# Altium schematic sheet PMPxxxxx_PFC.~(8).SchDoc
size 431 x 279 mm; Date: Not shown in title block; ApprovedBy: Not shown in title block; CheckedBy: Not shown in title block; Author: Not shown in title block; CompanyName: Not shown in title block; Engineer: Not shown in title block; Organization: Not shown in title block; Address1: Not shown in title block; Address2: Not shown in title block; Address3: Not shown in title block; Address4: Not shown in title block; DocumentNumber: 1; Revision: Use project parameter SCH_Rev; SheetNumber: 1; SheetTotal: 3; PageSetup: Record=PageOptions¦CenterHorizontal=True¦CenterVertical=True¦PrintScale=1.00¦XCorrection=1.00¦YCorrection=1.00¦PrintKind=0¦BorderSize=5000000¦LeftOffset=0¦BottomOffset=0¦Orientation=2¦PaperLength=1000¦PaperWidth=1000¦Scale=100¦PaperSource=15¦PrintQuality=600¦MediaType=1¦DitherType=10¦PaperKind=Letter¦PrintScaleMode=1
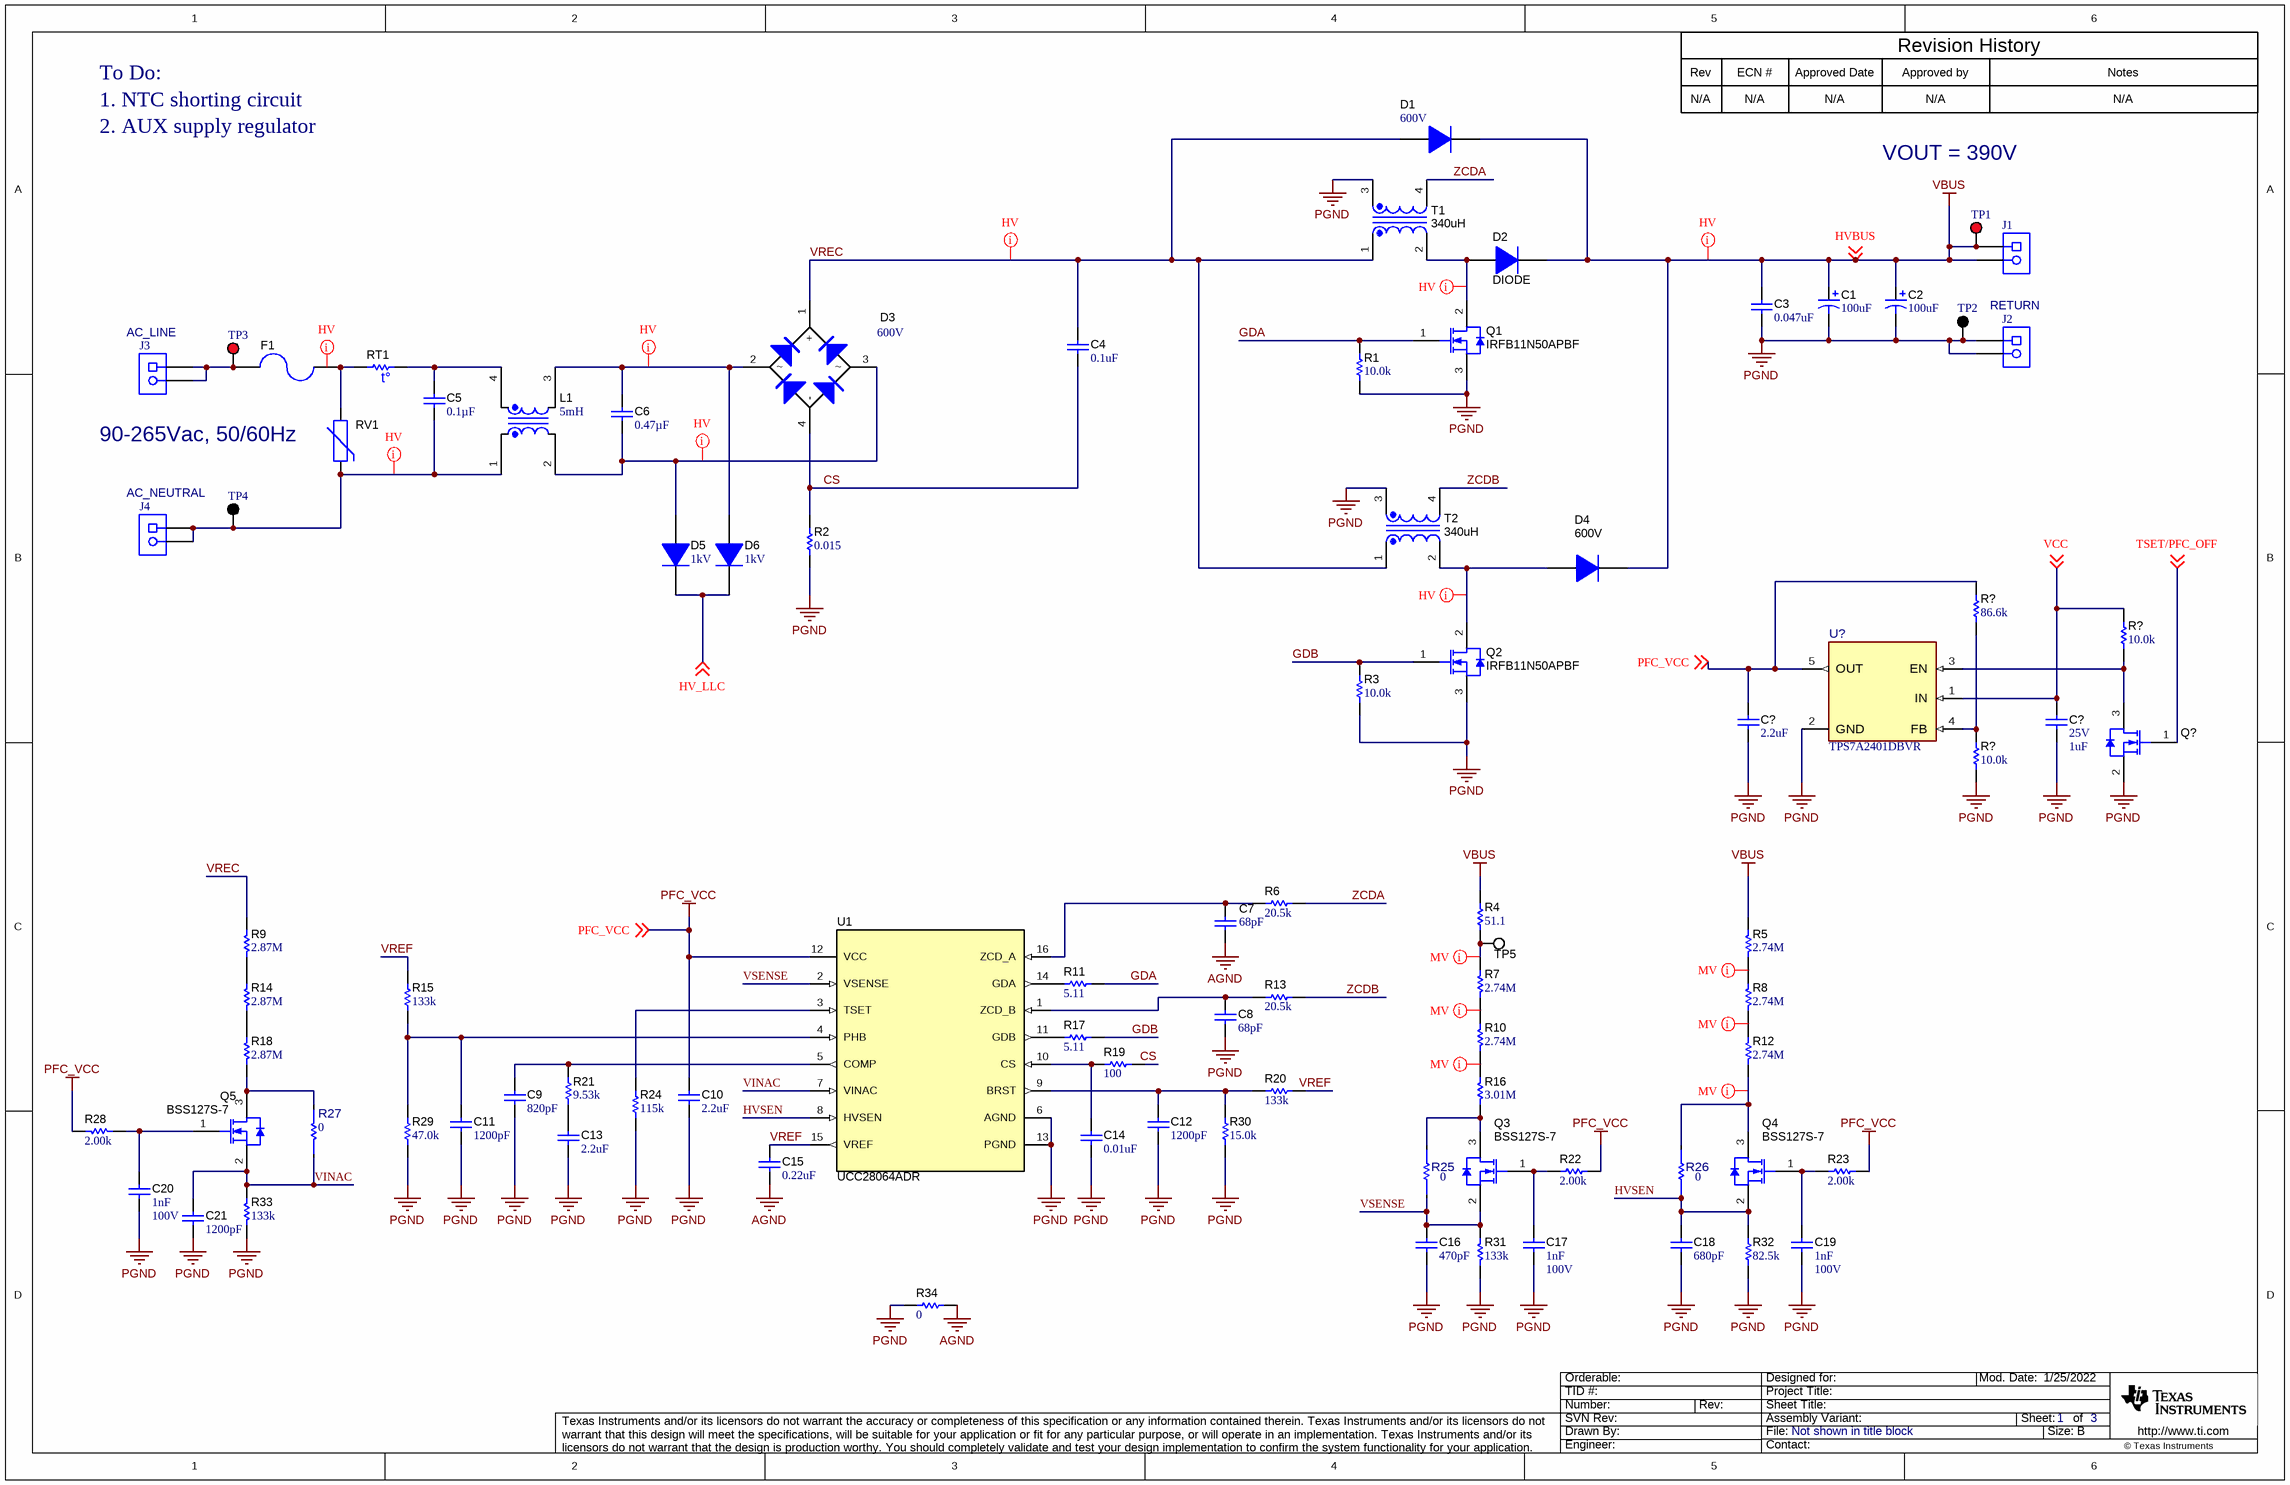
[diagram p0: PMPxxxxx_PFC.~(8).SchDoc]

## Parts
(Parts that share a designator on the sheet are numbered #1, #2 ... from top to bottom, then left to right.)
C1  ValueDisplayed: 100uF  [KXG_1800x4000_horizontalUp]  (hidden comment: Cap_Polarized)
C2  ValueDisplayed: 100uF  [KXG_1800x4000_horizontalDown]  (hidden comment: Cap_Polarized)
C3  ValueDisplayed: 0.047uF  [ECQE_1200x1450x650]  (hidden comment: Capacitor)
C4  ValueDisplayed: 0.1uF  [CAPRR1500W60L1750T550H1250]  (hidden comment: Capacitor)
C5  ValueDisplayed: 0.1µF  [Kemet_1800x500x1100]  (hidden comment: F863BC104K310Z)
C6  ValueDisplayed: 0.47µF  [PHE840M_2600x800x1600]  (hidden comment: PHE840MY6470MD14R06L2)
C7  ValueDisplayed: 68pF  [0805_HV]  (hidden comment: Capacitor)
C8  ValueDisplayed: 68pF  [0805_HV]  (hidden comment: Capacitor)
C9  ValueDisplayed: 820pF  [0805_HV]  (hidden comment: Capacitor)
C10  ValueDisplayed: 2.2uF  [0805_HV]  (hidden comment: Capacitor)
C11  ValueDisplayed: 1200pF  [0805_HV]  (hidden comment: Capacitor)
C12  ValueDisplayed: 1200pF  [0805_HV]  (hidden comment: Capacitor)
C13  ValueDisplayed: 2.2uF  [0805_HV]  (hidden comment: Capacitor)
C14  ValueDisplayed: 0.01uF  [0805_HV]  (hidden comment: Capacitor)
C15  ValueDisplayed: 0.22uF  [1206]  (hidden comment: Capacitor)
C16  ValueDisplayed: 470pF  [0805_HV]  (hidden comment: Capacitor)
C17  Cap_F: 1nF  VDC_V: 100V  [0603]  (hidden comment: C1608X7R2A102K080AA)
C18  ValueDisplayed: 680pF  [0805_HV]  (hidden comment: Capacitor)
C19  Cap_F: 1nF  VDC_V: 100V  [0603]  (hidden comment: C1608X7R2A102K080AA)
C20  Cap_F: 1nF  VDC_V: 100V  [0603]  (hidden comment: C1608X7R2A102K080AA)
C21  ValueDisplayed: 1200pF  [0805_HV]  (hidden comment: Capacitor)
C?#1  ValueDisplayed: 2.2uF  [0805_HV]  (hidden comment: Capacitor)
C?#2  VDC_V: 25V  ValueDisplayed: 1uF  [0603]  (hidden comment: C1608X5R1E105K080AC)
D1  Vr_V: 600V  [SMC]  (hidden comment: DIODE)
D2  DIODE  [SMC]
D3  Vr_V: 600V  [GBU_Horizontal_Down_Standoff2300]  (hidden comment: GBU6J)
D4  600V  [SMC]
D5  Vr_V: 1kV  [DO-41]  (hidden comment: 1N4007-E3/73)
D6  Vr_V: 1kV  [DO-41]  (hidden comment: 1N4007-E3/73)
F1  0216008.MXEP  [FUSE_0216]  (value not drawn)
J1  Receptacle_2x1  [On-Shore_ED120_2DS]  (value not drawn)
J2  Receptacle_2x1  [On-Shore_ED120_2DS]  (value not drawn)
J3  Receptacle_2x1  [On-Shore_ED120_2DS]  (value not drawn)
J4  Receptacle_2x1  [On-Shore_ED120_2DS]  (value not drawn)
L1  ValueDisplayed: 5mH  [8100_8109-8114]  (hidden comment: INDUCTOR_COUPLED_12_43)
Q1  IRFB11N50APBF  [TO-220AB_Horizontal_100mil_Standoff2300]
Q2  IRFB11N50APBF  [TO-220AB_Horizontal_100mil_Standoff2300]
Q3  BSS127S-7  [SOT-23]
Q4  BSS127S-7  [SOT-23]
Q5  BSS127S-7  [SOT-23]
Q?  2N7002-7-F  [SOT-23]  (value not drawn)
R1  ValueDisplayed: 10.0k  [0805_HV]  (hidden comment: Resistor)
R2  ValueDisplayed: 0.015  [2010]  (hidden comment: Resistor)
R3  ValueDisplayed: 10.0k  [0805_HV]  (hidden comment: Resistor)
R4  ValueDisplayed: 51.1  [0805_HV]  (hidden comment: Resistor)
R5  ValueDisplayed: 2.74M  [0805_HV]  (hidden comment: Resistor)
R6  ValueDisplayed: 20.5k  [0805_HV]  (hidden comment: Resistor)
R7  ValueDisplayed: 2.74M  [0805_HV]  (hidden comment: Resistor)
R8  ValueDisplayed: 2.74M  [0805_HV]  (hidden comment: Resistor)
R9  ValueDisplayed: 2.87M  [0805_HV]  (hidden comment: Resistor)
R10  ValueDisplayed: 2.74M  [0805_HV]  (hidden comment: Resistor)
R11  ValueDisplayed: 5.11  [0805_HV]  (hidden comment: Resistor)
R12  ValueDisplayed: 2.74M  [0805_HV]  (hidden comment: Resistor)
R13  ValueDisplayed: 20.5k  [0805_HV]  (hidden comment: Resistor)
R14  ValueDisplayed: 2.87M  [0805_HV]  (hidden comment: Resistor)
R15  ValueDisplayed: 133k  [0805_HV]  (hidden comment: CRCW0805133KFKEA)
R16  ValueDisplayed: 3.01M  [0805_HV]  (hidden comment: Resistor)
R17  ValueDisplayed: 5.11  [0805_HV]  (hidden comment: Resistor)
R18  ValueDisplayed: 2.87M  [0805_HV]  (hidden comment: Resistor)
R19  ValueDisplayed: 100  [0805_HV]  (hidden comment: Resistor)
R20  ValueDisplayed: 133k  [0805_HV]  (hidden comment: CRCW0805133KFKEA)
R21  ValueDisplayed: 9.53k  [0805_HV]  (hidden comment: Resistor)
R22  ValueDisplayed: 2.00k  [0603]  (hidden comment: RC0603FR-072KL)
R23  ValueDisplayed: 2.00k  [0603]  (hidden comment: RC0603FR-072KL)
R24  ValueDisplayed: 115k  [0805_HV]  (hidden comment: CRCW0805115KFKEA)
R25  value 0  [FP-RMCF1206ZT0R00_1206-MFG]  (hidden comment: RMCF1206ZT0R00)
R26  value 0  [FP-RMCF1206ZT0R00_1206-MFG]  (hidden comment: RMCF1206ZT0R00)
R27  value 0  [FP-RMCF1206ZT0R00_1206-MFG]  (hidden comment: RMCF1206ZT0R00)
R28  ValueDisplayed: 2.00k  [0603]  (hidden comment: RC0603FR-072KL)
R29  ValueDisplayed: 47.0k  [0805_HV]  (hidden comment: Resistor)
R30  ValueDisplayed: 15.0k  [0805_HV]  (hidden comment: CRCW080515K0FKEA)
R31  ValueDisplayed: 133k  [0805_HV]  (hidden comment: Resistor)
R32  ValueDisplayed: 82.5k  [0805_HV]  (hidden comment: Resistor)
R33  ValueDisplayed: 133k  [0805_HV]  (hidden comment: CRCW0805133KFKEA)
R34  ValueDisplayed: 0  [2512]  (hidden comment: Resistor)
R?#1  ValueDisplayed: 86.6k  [0603]  (hidden comment: RC0603FR-0786K6L)
R?#2  ValueDisplayed: 10.0k  [0603]  (hidden comment: M55342K12B10E0T)
R?#3  ValueDisplayed: 10.0k  [0603]  (hidden comment: M55342K12B10E0T)
RT1  CL-40  [Thermistor_CL-40]  (value not drawn)
RV1  Varistor_MetalOxide  [VAR_S10K275E2]  (value not drawn)
T1  340uH  [EATON_CTX16-17769-R]
T2  340uH  [EATON_CTX16-17769-R]
TP1  5010  [Keystone5010]  (value not drawn)
TP2  5011  [Keystone5011]  (value not drawn)
TP3  5010  [Keystone5010]  (value not drawn)
TP4  5011  [Keystone5011]  (value not drawn)
TP5  5002  [Keystone5002]  (value not drawn)
U1  UCC28064ADR  [D0016A_N]
U?  TPS7A2401DBVR  [DBV0005A-MFG]

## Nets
AGND: C7.2 C15.2 R34.1
PFC_VCC: C10.2 C?#1.2 R22.2 R23.2 R28.2 R?#1.1 U1.12(VCC) U?.5(OUT) ; off-sheet PFC_VCC
PGND: C1.2(-) C2.2(-) C3.2 C8.1 C9.1 C10.1 C11.2 C12.2 C13.2 C14.2 C16.2 C17.2 C18.2 C19.2 C20.2 C21.1 C?#1.1 C?#2.2 J2.1 J2.2 Q1.3(S) Q2.3(S) Q?.2(S) R1.1 R2.1 R3.1 R24.1 R29.1 R30.1 R31.1 R32.1 R33.1 R34.2 R?#3.1 T1.3 T2.3 TP2.1 U1.6(AGND) U1.13(PGND) U?.2(GND)
VBUS: C1.1(+) C2.1(+) C3.1 D1.1(K) D2.1(K) D4.1(K) J1.1 J1.2 R4.2 R5.2 TP1.1 ; off-sheet HVBUS  [also labelled HVBUS]
CS: C4.2 D3.4(-) R2.2 R19.2
GDA: Q1.1(G) R1.2 R11.2
GDB: Q2.1(G) R3.2 R17.2
HV_LLC: D5.1(K) D6.1(K) ; off-sheet HV_LLC
HVSEN: C18.1 Q4.2(S) R26.1 R32.2 U1.8(HVSEN)
TSET/PFC_OFF: Q?.1(G) ; off-sheet TSET/PFC_OFF
VCC: C?#2.1 R?#2.2 U?.1(IN) ; off-sheet VCC
VINAC: C21.2 Q5.2(S) R27.1 R33.2 U1.7(VINAC)
VREC: C4.1 D1.2(A) D3.1(+) R9.1 T1.1 T2.1
VREF: C15.1 R15.2 R20.2 U1.15(VREF)
VSENSE: C16.1 Q3.2(S) R25.1 R31.2 U1.2(VSENSE)
ZCDA: R6.1 T1.4
ZCDB: R13.2 T2.4
NetC5_1: C5.1 L1.4 RT1.2
NetC5_2: C5.2 J4.1 J4.2 L1.1 RV1.2 TP4.1
NetC6_1: C6.1 D3.2 D6.2(A) L1.3
NetC6_2: C6.2 D3.3 D5.2(A) L1.2
NetC7_1: C7.1 R6.2 U1.16(ZCD_A)
NetC8_2: C8.2 R13.1 U1.1(ZCD_B)
NetC9_2: C9.2 R21.2 U1.5(COMP)
NetC11_1: C11.1 R15.1 R29.2 U1.4(PHB)
NetC12_1: C12.1 R20.1 R30.2 U1.9(BRST)
NetC13_1: C13.1 R21.1
NetC14_1: C14.1 R19.1 U1.10(CS)
NetC17_1: C17.1 Q3.1(G) R22.1
NetC19_1: C19.1 Q4.1(G) R23.1
NetC20_1: C20.1 Q5.1(G) R28.1
NetD2_2: D2.2(A) Q1.2(D) T1.2
NetD4_2: D4.2(A) Q2.2(D) T2.2
NetF1_1: F1.1 RT1.1 RV1.1
NetF1_2: F1.2 J3.1 J3.2 TP3.1
NetQ3_3: Q3.3(D) R16.2 R25.2
NetQ4_3: Q4.3(D) R12.1 R26.2
NetQ5_3: Q5.3(D) R18.1 R27.2
NetQ?_3: Q?.3(D) R?#2.1 U?.3(EN)
NetR4_1: R4.1 R7.1 TP5.1
NetR5_1: R5.1 R8.2
NetR7_2: R7.2 R10.1
NetR8_1: R8.1 R12.2
NetR9_2: R9.2 R14.1
NetR10_2: R10.2 R16.1
NetR11_1: R11.1 U1.14(GDA)
NetR14_2: R14.2 R18.2
NetR17_1: R17.1 U1.11(GDB)
NetR24_2: R24.2 U1.3(TSET)
NetR?#1_2: R?#1.2 R?#3.2 U?.4(FB)

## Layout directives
net class HV: (no net found under the mark), NetC5_2, NetC6_1, NetC6_2, NetD2_2, NetD4_2, VBUS, VREC
net class MV: NetQ4_3, NetR4_1, NetR5_1, NetR7_2, NetR8_1, NetR10_2

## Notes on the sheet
- To Do:
- Rev
- N/A
- ECN #
- Approved Date
- Approved by
- Revision History
- Notes
- 1. NTC shorting circuit
- 2. AUX supply regulator
- VOUT = 390V
- (near J3) AC_LINE
- RETURN
- 90-265Vac, 50/60Hz
- (near J4) AC_NEUTRAL

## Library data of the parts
C1 C2 = CMP-0010042-2: CAP, AL, 100 uF, 450 V, +/- 20%, TH; PartNumber: EKXG451ELL101MM40S; Manufacturer: Chemi-Con; Polarized: Y; CompType: Capacitor; Value: 100uF; U/M: EA; Cap_F: 100µF; Value1: Unknown; VDC_V: 450V; IRMS_A: 8dA; TaMin_C: -25°C; TaMax_C: 105°C; Cap_Case: 18x40mm; SizeAreaWB_mm2: 400; SizeArea_mm2: 324; SizeX_mm: 18; SizeZ_mm: 41.5; AEC Category: Q200; AEC Qualified: N
C3 = CMP-0012494-3: CAP, Film, 0.047 uF, 630 V, +/- 10%, TH; PartNumber: ECQ-E6473KF; Manufacturer: Panasonic; Polarized: N; Cap_F: 47nF; Value1: Unknown; VDC_V: 630V; TaMin_C: -40°C; TaMax_C: 105°C; Cap_Case: 12x14.5x6.5mm; SizeAreaWB_mm2: 119; SizeArea_mm2: 78; SizeX_mm: 12; SizeY_mm: 6.5; SizeZ_mm: 14.5; AEC Category: Q200
C4 = CMP-0012496-3: CAP, Film, 0.1 uF, 275 V, +/- 20%, TH; PartNumber: ECQ-U2A104ML; Manufacturer: Panasonic; Polarized: N; Value: 0.1uF; Cap_F: 100nF; Value1: Unknown; VDC_V: 275V; TaMin_C: -40°C; TaMax_C: 100°C; Cap_Case: Radial 17.5x5.5x12.5; AEC Category: Q200
C5 = CMP-0079307-2: CAP, Film, 0.1 µF, X2 310 VAC, +/- 10%, AEC-Q200 Grade 1, TH; Manufacturer: Kemet; Cap_F: 100nF; SizeAreaWB_mm2: 140; SizeArea_mm2: 90; AEC Qualified: Y; AEC Category: Q200; Value: 0.1uF; TaMax_C: 110°C; SizeZ_mm: 11.1; AEC Grade: 1; Polarized: N; TaMin_C: -40°C; SizeY_mm: 5; CompType: Capacitor; SizeX_mm: 18; Cap_Case: 18x5x11mm; VAC_X: 310
C6 = CMP-0079470-1: CAP, Film, 0.47 µF, 760 V,+/- 20%, TH; Manufacturer: Kemet; Cap_F: 470nF; SizeAreaWB_mm2: 280; SizeArea_mm2: 208; AEC Qualified: N; AEC Category: Q200; Value: 0.47uF; TaMax_C: 105°C; SizeZ_mm: 16; TaMin_C: -55°C; VDC_V: 760V; SizeY_mm: 8; CompType: Capacitor; SizeX_mm: 26; Cap_Case: 26x8x16mm
C7 C8 = CMP-0007622-2: CAP, CERM, 68 pF, 50 V, +/- 5%, C0G/NP0, 0805; PartNumber: 08055A680JAT2A; Manufacturer: AVX; Polarized: N; Value: 68pF; U/M: EA; ESR_ohm: 4.5d; Value1: 0.45 ohm; VDC_V: 50V; TaMin_C: -55°C; TaMax_C: 125°C; Cap_Case: 0805; SizeArea_mm2: 2.5; SizeAreaWB_mm2: 6.75; SizeX_mm: 2; SizeY_mm: 1.25; SizeZ_mm: 1.45; AEC Category: Q200
C9 = CMP-0008153-2: CAP, CERM, 820 pF, 25 V, +/- 10%, X7R, 0805; PartNumber: GRM216R71E821KA01D; Manufacturer: MuRata; Polarized: N; Value: 820pF; U/M: EA; Value1: Unknown; VDC_V: 25V; TaMin_C: -55°C; TaMax_C: 125°C; Cap_Case: 0805; SizeArea_mm2: 2.5; SizeAreaWB_mm2: 6.75; SizeX_mm: 2; SizeY_mm: 1.25; SizeZ_mm: 1.45; AEC Category: Q200
C10 C13 C?#1 = CMP-0007877-2: CAP, CERM, 2.2 uF, 50 V, +/- 10%, X7R, 0805; PartNumber: C2012X7R1H225K125AC; Manufacturer: TDK; Polarized: N; Value: 2.2uF; U/M: EA; Cap_F: 2.2µF; ESR_ohm: 3.66m; Value1: 0.00366 ohm; VDC_V: 50V; IRMS_A: 3.41207A; TaMin_C: -55°C; TaMax_C: 125°C; Cap_Case: 0805; SizeArea_mm2: 2.5; SizeAreaWB_mm2: 6.75; SizeX_mm: 2; SizeY_mm: 1.25; SizeZ_mm: 1.45; AEC Category: Q200
C11 C12 C21 = CMP-0008142-2: CAP, CERM, 1200 pF, 25 V, +/- 10%, X7R, 0805; PartNumber: GRM216R71E122KA01D; Manufacturer: MuRata; Polarized: N; Value: 1200pF; U/M: EA; Cap_F: 1.2nF; Value1: Unknown; VDC_V: 25V; TaMin_C: -55°C; TaMax_C: 125°C; Cap_Case: 0805; SizeArea_mm2: 2.5; SizeAreaWB_mm2: 6.75; SizeX_mm: 2; SizeY_mm: 1.25; SizeZ_mm: 1.45; AEC Category: Q200
C14 = CMP-0007629-2: CAP, CERM, 0.01 uF, 50 V, +/- 5%, X7R, 0805; PartNumber: 08055C103JAT2A; Manufacturer: AVX; Polarized: N; Value: 0.01uF; U/M: EA; Cap_F: 10nF; ESR_ohm: 0.078; Value1: 0.078 ohm; VDC_V: 50V; TaMin_C: -55°C; TaMax_C: 125°C; Cap_Case: 0805; SizeArea_mm2: 2.5; SizeAreaWB_mm2: 6.75; SizeX_mm: 2; SizeY_mm: 1.25; SizeZ_mm: 1.45; AEC Category: Q200
C15 = CMP-0008995-2: CAP, CERM, 0.22 uF, 50 V, +/- 10%, X7R, 1206; PartNumber: GRM31MR71H224KA01L; Manufacturer: MuRata; Polarized: N; Value: 0.22uF; U/M: EA; Cap_F: 220nF; Value1: Unknown; VDC_V: 50V; TaMin_C: -55°C; TaMax_C: 125°C; SizeArea_mm2: 5.12; SizeAreaWB_mm2: 10.92; SizeX_mm: 3.2; SizeY_mm: 1.6; SizeZ_mm: 1.35; AEC Category: Q200
C16 = CMP-0008150-2: CAP, CERM, 470 pF, 25 V, +/- 10%, X7R, 0805; PartNumber: GRM216R71E471KA01D; Manufacturer: MuRata; Polarized: N; Value: 470pF; U/M: EA; Value1: Unknown; VDC_V: 25V; TaMin_C: -55°C; TaMax_C: 125°C; Cap_Case: 0805; SizeArea_mm2: 2.5; SizeAreaWB_mm2: 6.75; SizeX_mm: 2; SizeY_mm: 1.25; SizeZ_mm: 1.45; AEC Category: Q200
C17 C19 C20 = CMP-0007053-4: CAP, CERM, 1000 pF, 100 V, +/- 10%, X7R, 0603; Manufacturer: TDK; TaMin_C: -55°C; Polarized: N; SizeAreaWB_mm2: 4.68; Value1: Unknown; U/M: EA; Value: 1000pF; TaMax_C: 125°C; SizeZ_mm: 1; SizeX_mm: 1.6; SizeY_mm: 0.8; SizeArea_mm2: 1.28; AEC Category: Q200
C18 = CMP-0007693-2: CAP, CERM, 680 pF, 25 V, +/- 10%, X7R, 0805; PartNumber: 885012207059; Manufacturer: Wurth Elektronik; Polarized: N; Value: 680pF; U/M: EA; Value1: Unknown; VDC_V: 25V; TaMin_C: -55°C; TaMax_C: 125°C; Cap_Case: 0805; SizeArea_mm2: 2.5; SizeAreaWB_mm2: 6.75; SizeX_mm: 2; SizeY_mm: 1.25; SizeZ_mm: 1.45; AEC Category: Q200
C?#2 = CMP-0007006-5: CAP, CERM, 1 uF, 25 V, +/- 10%, X5R, 0603; Manufacturer: TDK; TaMin_C: -55°C; Polarized: N; SizeAreaWB_mm2: 4.68; Value1: Unknown; U/M: EA; Value: 1uF; TaMax_C: 85°C; SizeZ_mm: 1; SizeX_mm: 1.6; SizeY_mm: 0.8; SizeArea_mm2: 1.28; Cap_F: 1µF; AEC Category: Q200
D1 D2 = CMP-0076905-1: Diode, Ultrafast, 600 V, 3 A, SMC; PartNumber: MURS360T3G; Manufacturer: ON Semiconductor; U/M: EA; Vf_V: 1.25V; Value: 600V; Value1: 3A; TJmax_C: 175°C; RJC_CperW: 11.0; SizeAreaWB_mm2: 83.2686; SizeArea_mm2: 50.5686; SizeX_mm: 8.13; SizeY_mm: 6.22; SizeZ_mm: 2.6; AEC Category: Q101; Green_Lifecycle: Active; Green_REACh: Passed
D3 = CMP-0029269-2: Diode, Switching-Bridge, 600 V, 6 A, TH; Manufacturer: Fairchild Semiconductor; U/M: EA; Vf_V: 1V; Value: 600V; Value1: 6A; TJmax_C: 150°C; RJC_CperW: 3.1; SizeAreaWB_mm2: 130.5915; SizeArea_mm2: 75.6315; SizeX_mm: 22.05; SizeY_mm: 3.43; SizeZ_mm: 21.55; AEC Category: Q101; AEC Qualified: N; Green_Lifecycle: Active; Green_REACh: Passed
D4 = CMP-0076905-1: Diode, Ultrafast, 600 V, 3 A, SMC; PartNumber: MURS360T3G; Manufacturer: ON Semiconductor; U/M: EA; Vf_V: 1.25V; Value1: 3A; TJmax_C: 175°C; RJC_CperW: 11.0; SizeAreaWB_mm2: 83.2686; SizeArea_mm2: 50.5686; SizeX_mm: 8.13; SizeY_mm: 6.22; SizeZ_mm: 2.6; AEC Category: Q101; Green_Lifecycle: Active; Green_REACh: Passed
D5 D6 = CMP-0029188-2: Diode, P-N, 1000 V, 1 A, TH; Manufacturer: Vishay-Semiconductor; Io_A: 1A; SizeAreaWB_mm2: 43.424; TJmax_C: 150°C; Value: 1000V; SizeZ_mm: 23.4; SizeX_mm: 7.2; SizeY_mm: 2.72; Vf_V: 1.1V; SizeArea_mm2: 19.584; AEC Qualified: N; AEC Category: Q101
F1 = CMP-0079917-1: Fuse, 8 A, 250 VAC, TH; Manufacturer: Littelfuse; VAC_V: 250V; Rtyp_Ohm: 0.0123; MeltingTyp: 64.315; Irating_A: 8A; Interrupt_AC: 1.5kA
J1-J4 = CMP-0074910-1: Terminal Block, 5.08 mm, 2x1, Brass, TH; PartNumber: ED120/2DS; Manufacturer: On-Shore Technology; Pitch_mm: 5.08; Gender: Female; Shrouded: N; Row_Count: 1; Current_A: 15A; Voltage_V: 300V; Cert_CULUS: Y; Green_Lifecycle: Not Set; Green_REACh: Incomplete; CNHeader: False; CT: True
L1 = CMP-0076835-1: Coupled inductor, 5 mH, 8.9 A, 0.022 ohm, TH; PartNumber: 8113-RC; Manufacturer: Bourns; Value: 5mH; DCR_ohm: 0.022; Green_Lifecycle: Not Set; Green_REACh: Incomplete; AEC Category: Q200
Q1 Q2 = CMP-0001125-3: MOSFET, N-CH, 500 V, 11 A, AEC-Q101, TO-220AB; Alternate Manufacturer: None; Manufacturer: Vishay-Siliconix; SizeZ_mm: 19.4; ChType: N; Value2: 52 nC; VdsMax_V: 500V; SizeX_mm: 10.2; SizeY_mm: 4.5; Vgs_V: 30V; AEC Qualified: Y; Value: 500V; SizeArea_mm2: 45.9; AEC Category: Q101; IdsMax_A: 11A; SizeAreaWB_mm2: 79.3; U/M: EA; QgTyp_nC: 52
Q3-Q5 = CMP-0001149-3: MOSFET, N-CH, 600 V, 0.05 A, SOT-23; Alternate Manufacturer: None; Manufacturer: Diodes Inc.; SizeZ_mm: 1.1; ChType: N; Value2: 1.08 nC; VdsMax_V: 600V; SizeX_mm: 2.5; SizeY_mm: 3; Vgs_V: 20V; QgTyp_nC: 1.08; Value: 600V; SizeArea_mm2: 7.5; AEC Category: Q101; IdsMax_A: 50mA; SizeAreaWB_mm2: 14; U/M: EA
Q? = CMP-0000769-1: MOSFET, N-CH, 60 V, 0.17 A, SOT-23; Alternate Manufacturer: None; Manufacturer: Diodes Inc.; SizeZ_mm: 1.1; ChType: N; Value2: 223 nC; Value1: 7; VdsMax_V: 60V; SizeX_mm: 2.5; SizeY_mm: 3; Vgs_V: 20V; Value: 60V; Rdson45_ohm: 7.5; AEC Category: Q101; IdsMax_A: 1.7dA; SizeAreaWB_mm2: 14; U/M: EA; QgTyp_nC: 223
R1 R3 = CMP-0020842-3: RES, 10.0 k, 1%, 0.125 W, AEC-Q200 Grade 0, 0805; PartNumber: CRCW080510K0FKEA; Manufacturer: Vishay-Dale; Value: 10.0k; Res_ohm: 10k; Value_Code: 10k0; Power_W: 125mW; Value2: 0.125W; VDC_V: 150V; TempCo: 100 ppm/C; SizeArea_mm2: 2.5; SizeX_mm: 2; SizeY_mm: 1.25; SizeZ_mm: 1.45; EIA_Code: E96; AEC Category: Q200; AEC Qualified: Y; AEC Grade: 0
R2 = CMP-0016558-2: RES, 0.015, 1%, 0.5 W, 2010; PartNumber: WSL2010R0150FEA; Manufacturer: Vishay-Dale; Value: 0.015; Value_Code: R015; Power_W: 500mW; Value2: 0.5W; TempCo: 75 ppm/C; SizeArea_mm2: 12.5; SizeX_mm: 5; SizeY_mm: 2.5; SizeZ_mm: 1.66; EIA_Code: E96; U/M: EA; AEC Category: Q200
R4 = CMP-0020156-2: RES, 51.1, 0.1%, 0.125 W, 0805; PartNumber: RT0805BRD0751R1L; Manufacturer: Yageo America; Value: 51.1; Value_Code: 51R1; Power_W: 125mW; Value2: 0.125W; VDC_V: 150V; TempCo: 25 ppm/C; SizeArea_mm2: 2.5; SizeX_mm: 2; SizeY_mm: 1.25; SizeZ_mm: 1.45; EIA_Code: E192; U/M: EA; AEC Category: Q200
R5 R7 R8 R10 R12 = CMP-0021137-3: RES, 2.74 M, 1%, 0.125 W, AEC-Q200 Grade 0, 0805; PartNumber: CRCW08052M74FKEA; Manufacturer: Vishay-Dale; Value: 2.74Meg; Value_Code: 2M74; Power_W: 125mW; Value2: 0.125W; VDC_V: 150V; TempCo: 100 ppm/C; SizeArea_mm2: 2.5; SizeX_mm: 2; SizeY_mm: 1.25; SizeZ_mm: 1.45; EIA_Code: E96; AEC Category: Q200; AEC Qualified: Y; AEC Grade: 0
R6 R13 = CMP-0021043-3: RES, 20.5 k, 1%, 0.125 W, AEC-Q200 Grade 0, 0805; PartNumber: CRCW080520K5FKEA; Manufacturer: Vishay-Dale; Value: 20.5k; Value_Code: 20k5; Power_W: 125mW; Value2: 0.125W; VDC_V: 150V; TempCo: 100 ppm/C; SizeArea_mm2: 2.5; SizeX_mm: 2; SizeY_mm: 1.25; SizeZ_mm: 1.45; EIA_Code: E96; AEC Category: Q200; AEC Qualified: Y; AEC Grade: 0
R9 R14 R18 = CMP-0021139-3: RES, 2.87 M, 1%, 0.125 W, AEC-Q200 Grade 0, 0805; PartNumber: CRCW08052M87FKEA; Manufacturer: Vishay-Dale; Value: 2.87Meg; Value_Code: 2M87; Power_W: 125mW; Value2: 0.125W; VDC_V: 150V; TempCo: 100 ppm/C; SizeArea_mm2: 2.5; SizeX_mm: 2; SizeY_mm: 1.25; SizeZ_mm: 1.45; EIA_Code: E96; AEC Category: Q200; AEC Qualified: Y; AEC Grade: 0
R11 R17 = CMP-0021358-3: RES, 5.11, 1%, 0.125 W, AEC-Q200 Grade 0, 0805; PartNumber: CRCW08055R11FKEA; Manufacturer: Vishay-Dale; Value: 5.11; Value_Code: 5R11; Power_W: 125mW; Value2: 0.125W; VDC_V: 150V; TempCo: 100 ppm/C; SizeArea_mm2: 2.5; SizeX_mm: 2; SizeY_mm: 1.25; SizeZ_mm: 1.45; EIA_Code: E96; AEC Category: Q200; AEC Qualified: Y; AEC Grade: 0
R15 R20 R33 = CMP-0020881-3: RES, 133 k, 1%, 0.125 W, AEC-Q200 Grade 0, 0805; Manufacturer: Vishay-Dale; Power_W: 125mW; TempCo: 100 ppm/C; Value: 133k; EIA_Code: E96; SizeX_mm: 2; SizeY_mm: 1.25; SizeZ_mm: 1.45; Value2: 0.125W; SizeArea_mm2: 2.5; AEC Qualified: Y; VDC_V: 150V; AEC Category: Q200; AEC Grade: 0
R16 = CMP-0021219-4: RES, 3.01 M, 1%, 0.125 W, AEC-Q200 Grade 0, 0805; PartNumber: CRCW08053M01FKEA; Manufacturer: Vishay-Dale; Value: 3.01Meg; Value_Code: 3M01; Power_W: 125mW; Value2: 0.125W; VDC_V: 150V; TempCo: 100 ppm/C; SizeArea_mm2: 2.5; SizeX_mm: 2; SizeY_mm: 1.25; SizeZ_mm: 1.45; EIA_Code: E96; AEC Category: Q200; AEC Qualified: Y; AEC Grade: 0
R19 = CMP-0020835-3: RES, 100, 1%, 0.125 W, AEC-Q200 Grade 0, 0805; PartNumber: CRCW0805100RFKEA; Manufacturer: Vishay-Dale; Value: 100; Value_Code: 100R; Power_W: 125mW; Value2: 0.125W; VDC_V: 150V; TempCo: 100 ppm/C; SizeArea_mm2: 2.5; SizeX_mm: 2; SizeY_mm: 1.25; SizeZ_mm: 1.45; EIA_Code: E96; AEC Category: Q200; AEC Qualified: Y; AEC Grade: 0
R21 = CMP-0021817-2: RES, 9.53 k, 1%, 0.125 W, 0805; PartNumber: ERJ-6ENF9531V; Manufacturer: Panasonic; Value: 9.53k; Value_Code: 9k53; Power_W: 125mW; Value2: 0.125W; TempCo: 100 ppm/C; SizeArea_mm2: 2.5; SizeX_mm: 2; SizeY_mm: 1.25; SizeZ_mm: 1.45; EIA_Code: E96; U/M: EA; AEC Category: Q200
R22 R23 R28 = CMP-0023000-5: RES, 2.00 k, 1%, 0.1 W, 0603; Manufacturer: Yageo; Power_W: 100mW; TempCo: 100 ppm/C; Value_Code: 2k00; Value: 2.00k; EIA_Code: E96; Res_ohm: 2k; SizeX_mm: 1.6; SizeY_mm: 0.8; SizeZ_mm: 1; Value2: 0.1W; SizeArea_mm2: 1.28; AEC Qualified: N; VDC_V: 75V; AEC Category: Q200; SizeAreaWB_mm2: 4.68
R24 = CMP-0020855-3: RES, 115 k, 1%, 0.125 W, AEC-Q200 Grade 0, 0805; Manufacturer: Vishay-Dale; Power_W: 125mW; TempCo: 100 ppm/C; Value: 115k; EIA_Code: E96; SizeX_mm: 2; SizeY_mm: 1.25; SizeZ_mm: 1.45; Value2: 0.125W; SizeArea_mm2: 2.5; AEC Qualified: Y; VDC_V: 150V; AEC Category: Q200; AEC Grade: 0
R25-R27 = CMP-0093609-1: 0Ω ±0 0.25W 1206 Thick Film Chip Resistor AEC-Q200 compliant; Manufacturer: Stackpole Electronics; AEC Qualified: Yes; VDC_V: 200V; AEC Grade: Grade 0; Power_W: 250mW; SizeZ_mm: 0.7mm
R29 = CMP-0021726-2: RES, 47.0 k, 1%, 0.125 W, 0805; PartNumber: ERJ-6ENF4702V; Manufacturer: Panasonic; Value: 47.0k; Res_ohm: 47k; Value_Code: 47k0; Power_W: 125mW; Value2: 0.125W; VDC_V: 150V; TempCo: 100 ppm/C; SizeArea_mm2: 2.5; SizeX_mm: 2; SizeY_mm: 1.25; SizeZ_mm: 1.45; U/M: EA; AEC Category: Q200
R30 = CMP-0020909-3: RES, 15.0 k, 1%, 0.125 W, AEC-Q200 Grade 0, 0805; Manufacturer: Vishay-Dale; Power_W: 125mW; TempCo: 100 ppm/C; Value_Code: 15k0; Value: 15.0k; EIA_Code: E96; Res_ohm: 15k; SizeX_mm: 2; SizeY_mm: 1.25; SizeZ_mm: 1.45; Value2: 0.125W; SizeArea_mm2: 2.5; AEC Qualified: Y; VDC_V: 150V; AEC Category: Q200; AEC Grade: 0
R31 = CMP-0020881-3: RES, 133 k, 1%, 0.125 W, AEC-Q200 Grade 0, 0805; PartNumber: CRCW0805133KFKEA; Manufacturer: Vishay-Dale; Value: 133k; Power_W: 125mW; Value2: 0.125W; VDC_V: 150V; TempCo: 100 ppm/C; SizeArea_mm2: 2.5; SizeX_mm: 2; SizeY_mm: 1.25; SizeZ_mm: 1.45; EIA_Code: E96; AEC Category: Q200; AEC Qualified: Y; AEC Grade: 0
R32 = CMP-0021455-3: RES, 82.5 k, 1%, 0.125 W, AEC-Q200 Grade 0, 0805; PartNumber: CRCW080582K5FKEA; Manufacturer: Vishay-Dale; Value: 82.5k; Value_Code: 82k5; Power_W: 125mW; Value2: 0.125W; VDC_V: 150V; TempCo: 100 ppm/C; SizeArea_mm2: 2.5; SizeX_mm: 2; SizeY_mm: 1.25; SizeZ_mm: 1.45; EIA_Code: E96; AEC Category: Q200; AEC Qualified: Y; AEC Grade: 0
R34 = CMP-0015864-3: RES, 0, 5%, 1 W, AEC-Q200 Grade 0, 2512; PartNumber: CRCW25120000Z0EG; Manufacturer: Vishay-Dale; Value: 0; Value_Code: 0000; Power_W: 1W; TempCo: ppm/C; SizeArea_mm2: 20.16; SizeX_mm: 6.3; SizeY_mm: 3.2; SizeZ_mm: 0.71; EIA_Code: E24; AEC Category: Q200; AEC Qualified: Y
R?#1 = CMP-0023301-5: RES, 86.6 k, 1%, 0.1 W, 0603; Manufacturer: Yageo; Power_W: 100mW; TempCo: 100 ppm/C; Value_Code: 86k6; Value: 86.6k; EIA_Code: E96; SizeX_mm: 1.6; SizeY_mm: 0.8; SizeZ_mm: 1; Value2: 0.1W; SizeArea_mm2: 1.28; AEC Qualified: N; VDC_V: 75V; AEC Category: Q200; SizeAreaWB_mm2: 4.68
R?#2 R?#3 = CMP-0080488-1: RES, 10.0 k, 1%, 0.1 W, 0603; Manufacturer: TT Electronics/IRC; Power_W: 100mW; TempCo: 100 ppm/C; SizeAreaWB_mm2: 4.68; Value_Code: 10k0; Value: 10.0k; EIA_Code: E96; Res_ohm: 10k; SizeX_mm: 1.6; SizeY_mm: 0.8; SizeZ_mm: 1; Value2: 0.1W; SizeArea_mm2: 1.28; AEC Qualified: N; AEC Category: Q200
RT1 = CMP-0002561-2: Thermistor NTC, 5 ohm, 25%, Disc, 220x770 mil; Manufacturer: GE Sensing; Value: 5; Power_W: 180W; TaMin_C: -50°C; TaMax_C: 175°C; SizeAreaWB_mm2: 163.6404; SizeArea_mm2: 109.3404; SizeX_mm: 19.56; SizeY_mm: 5.59; U/M: EA
RV1 = CMP-0002100-2: Varistor 275V RMS 10MM Radial, TH; PartNumber: S10K275E2; Manufacturer: TDK; SizeAreaWB_mm2: 103.6; SizeArea_mm2: 64.8; SizeX_mm: 12; SizeY_mm: 5.4; SizeZ_mm: 14.5
T1 T2 = CMP-0030075-1: Transformer, 340 uH, TH; PartNumber: CTX16-17769-R; Manufacturer: Eaton; DCR_ohm: 2.4d; Lp: 340; Ind_H: 340µH; Ns1toNp: 8; Rsec1_ohm: 0.035; SizeAreaWB_mm2: 1764; SizeArea_mm2: 1600; SizeX_mm: 40; SizeZ_mm: 19.8
TP1 TP3 = CMP-0055147-2: Test Point, Multipurpose, Red, TH; Manufacturer: Keystone Electronics; CT: TRUE; ContactFinish: Silver; Green_Lifecycle: Active; CNHeader: FALSE; Green_REACh: Passed
TP2 TP4 = CMP-0055148-2: Test Point, Multipurpose, Black, TH; Manufacturer: Keystone Electronics; CNHeader: FALSE; ContactFinish: Silver; Green_REACh: Passed; Green_Lifecycle: Active; CT: TRUE
TP5 = CMP-0055139-1: Test Point, Miniature, White, TH; Manufacturer: Keystone; CNHeader: FALSE; Green_Lifecycle: Active; Green_REACh: Passed; ContactFinish: Silver; CT: TRUE
U1 = CMP-0065070-4: Natural Interleaving Transition Mode PFC Controller with Improved Light Load Efficiency, D0016A (SOIC-16); Manufacturer: Texas Instruments; SizeX_mm: 6.0; SizeY_mm: 9.9; CompType: IC; SizeZ_mm: 1.75; SizeArea_mm2: 59.4; SizeAreaWB_mm2: 95.2; U/M: EA
U? = CMP-0089843-1: Linear Voltage Regulator IC 1 Output 200mA SOT-23-5; Manufacturer: Texas Instruments; Output Type: AdjustableProgrammable; Accuracy Percentage: 2%; AEC Qualified: No; Max Supply Voltage: 18V; Dropout Voltage: 160mV; SizeZ_mm: 1.45mm; Output Voltage: 1.24-17.75V; Min Supply Voltage: 2.4V; TJmax_C: +125°C; Nominal Supply Current: 2uA; Number Of Outputs: 1; Standoff Height: 0mm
